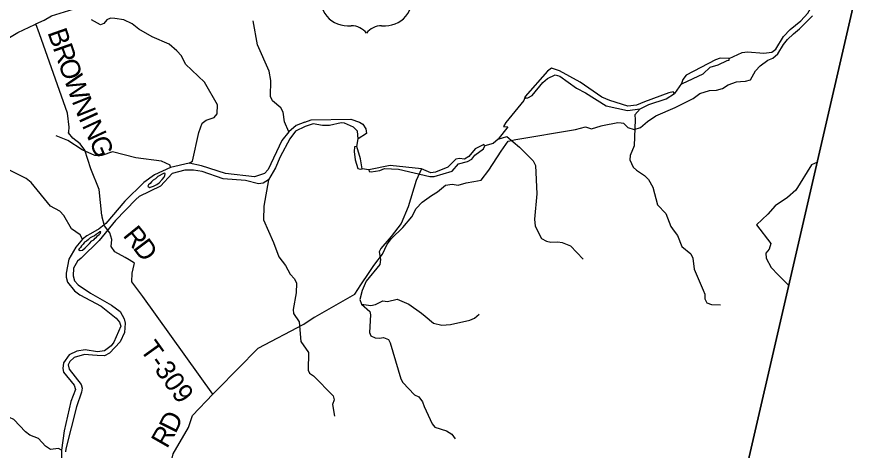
# Model space of a CAD drawing. Extents: x 1525783 to 1900577, y 218250 to 627376.
# Drawn here: x 1716205 to 1729274, y 441556 to 448212 of the extents above; entities that cross this region are included whole.
import ezdxf

# ---------------------------------------------------------------- set-up
doc = ezdxf.new("R2010")
doc.units = 0
for name, color, linetype in [('GM_X_Adjacent_County', 7, 'Continuous'), ('GM_X_County', 7, 'Continuous'), ('GM_X_Major_River', 7, 'Continuous'), ('GM_X_Minor_River', 7, 'Continuous'), ('GM_X_Township', 7, 'Continuous'), ('GM_X_Township_Road', 7, 'Continuous'), ('GM_X_Township_Road_Text', 7, 'Continuous'), ('GM_X_US_Route', 7, 'Continuous'), ('GM_X_US_Shield', 7, 'Continuous')]:
    doc.layers.add(name, color=color, linetype=linetype)

msp = doc.modelspace()

# ---------------------------------------------------------------- linework, layer by layer
at = {"layer": 'GM_X_Adjacent_County'}
msp.add_lwpolyline([(1727145, 440204), (1729274, 449424)], dxfattribs=at)
at = {"layer": 'GM_X_County'}
msp.add_lwpolyline([(1729274, 449424), (1727145, 440204)], dxfattribs=at)
at = {"layer": 'GM_X_Major_River'}
for points in [[(1727131, 447578), (1727328, 447668), (1727409, 447677), (1727661, 447657), (1727783, 447676), (1727846, 447719), (1727963, 447914), (1728063, 448021), (1728231, 448156), (1728337, 448271), (1728405, 448390), (1728503, 448708)], [(1727131, 447578), (1726992, 447580), (1726922, 447558), (1726472, 447321), (1726421, 447254), (1726400, 447192)], [(1726416, 447192), (1726731, 447342), (1726840, 447443), (1726961, 447478), (1727098, 447544)], [(1727098, 447544), (1727127, 447552), (1727131, 447578)], [(1726203, 447048), (1725829, 446914), (1725710, 446860), (1725577, 446845), (1725300, 446931), (1725177, 446985), (1724845, 447212), (1724527, 447388), (1724405, 447428), (1724343, 447380), (1724002, 446992)], [(1724042, 446971), (1724105, 447008), (1724270, 447207), (1724343, 447270), (1724462, 447327), (1724532, 447308), (1724790, 447122), (1724925, 447048), (1725243, 446850), (1725572, 446777), (1725763, 446803), (1725898, 446873), (1726164, 446958), (1726290, 447041)], [(1726400, 447192), (1726290, 447041)], [(1726400, 447192), (1726416, 447192)], [(1724002, 446992), (1723978, 446932), (1723704, 446596), (1723669, 446534), (1723735, 446528), (1723584, 446341), (1723511, 446274), (1723380, 446236)], [(1724002, 446992), (1724011, 446968), (1724042, 446971)], [(1726290, 447041), (1726271, 447063), (1726203, 447048)], [(1720621, 446599), (1720486, 446550), (1720374, 446449), (1720269, 446321), (1720058, 445873), (1719999, 445814), (1719850, 445759), (1719402, 445811), (1719035, 445932), (1718847, 445971), (1718557, 445902), (1718315, 445794), (1718152, 445673), (1717860, 445389), (1717565, 445047), (1717463, 444963), (1717333, 444887), (1717278, 444856), (1717209, 444807), (1717107, 444684), (1717001, 444500), (1716961, 444286), (1716957, 444224), (1716980, 444145), (1717086, 444013), (1717167, 443953), (1717494, 443777), (1717725, 443594), (1717778, 443533), (1717795, 443468), (1717692, 443227), (1717651, 443168), (1717545, 443091), (1717441, 443075), (1717251, 443105), (1717122, 443087), (1717003, 443031), (1716916, 442906), (1716907, 442822), (1716918, 442766), (1717082, 442566), (1717101, 442497), (1717031, 442316), (1716926, 441864), (1716885, 441566), (1716894, 441305)], [(1720621, 446599), (1720719, 446638), (1721326, 446648), (1721458, 446602), (1721510, 446568), (1721555, 446495), (1721566, 446425), (1721438, 446346)], [(1720748, 446575), (1720626, 446531)], [(1721438, 446346), (1721430, 446460), (1721369, 446521), (1721231, 446585), (1721177, 446588), (1720996, 446548), (1720892, 446549), (1720748, 446575)], [(1720626, 446531), (1720478, 446461), (1720390, 446345), (1720240, 446067), (1720171, 445897), (1720061, 445715), (1719982, 445662), (1719910, 445655), (1719708, 445705), (1719368, 445729), (1719045, 445845), (1718913, 445866), (1718777, 445866), (1718586, 445811), (1718407, 445620), (1718080, 445457), (1718027, 445412), (1717718, 445093), (1717465, 444784), (1717188, 444514), (1717133, 444465), (1717072, 444358), (1717064, 444242), (1717087, 444167), (1717144, 444106), (1717332, 443976), (1717655, 443792), (1717786, 443697), (1717848, 443584), (1717864, 443515), (1717852, 443375), (1717785, 443228), (1717625, 443056), (1717546, 443017), (1717436, 443019), (1717364, 443026), (1717242, 443037), (1717080, 442989), (1717017, 442930), (1716992, 442879), (1717007, 442812), (1717187, 442576), (1717206, 442520), (1717196, 442458), (1717116, 442232), (1716955, 441591), (1716948, 441541)], [(1721416, 446224), (1721438, 446346)], [(1721384, 446220), (1721375, 446148), (1721394, 446020), (1721434, 445891)], [(1721416, 446224), (1721384, 446220)], [(1721498, 445884), (1721476, 446037), (1721416, 446224)], [(1723365, 446259), (1723234, 446191), (1723138, 446072), (1723069, 446031), (1722995, 446043), (1722935, 446032), (1722815, 445909), (1722623, 445834), (1722551, 445824), (1722479, 445851), (1722410, 445886), (1721931, 445933), (1721602, 445868)], [(1721639, 445840), (1721772, 445856), (1721841, 445888), (1722055, 445877), (1722538, 445768), (1722606, 445766), (1722882, 445846), (1722976, 445963), (1723115, 445998), (1723183, 446033), (1723226, 446093), (1723362, 446191)], [(1723362, 446191), (1723380, 446236)], [(1723380, 446236), (1723365, 446259)], [(1718367, 445765), (1718329, 445733), (1718295, 445710), (1718268, 445684), (1718246, 445658), (1718223, 445637), (1718213, 445619), (1718237, 445600), (1718301, 445617), (1718352, 445645), (1718388, 445668), (1718433, 445720), (1718461, 445755), (1718472, 445781), (1718478, 445805), (1718474, 445819), (1718452, 445812)], [(1718452, 445812), (1718367, 445765)], [(1721434, 445891), (1721471, 445878), (1721498, 445884)], [(1721602, 445868), (1721498, 445884)], [(1721602, 445868), (1721608, 445841), (1721639, 445840)], [(1717351, 444777), (1717383, 444796), (1717403, 444818), (1717424, 444838), (1717442, 444858), (1717464, 444877), (1717487, 444895), (1717491, 444917), (1717475, 444917), (1717449, 444896), (1717418, 444876), (1717394, 444858)], [(1717394, 444858), (1717358, 444839), (1717329, 444823), (1717299, 444802), (1717269, 444774), (1717242, 444758), (1717218, 444727), (1717195, 444703), (1717177, 444677), (1717150, 444645), (1717172, 444633), (1717208, 444638), (1717249, 444672), (1717292, 444714), (1717316, 444741), (1717351, 444777)]]:
    msp.add_lwpolyline(points, dxfattribs=at)
at = {"layer": 'GM_X_Minor_River'}
for points in [[(1718847, 445971), (1718898, 446002), (1718992, 446442), (1719043, 446584), (1719104, 446631), (1719229, 446669), (1719274, 446726), (1719279, 446868), (1719081, 447213), (1718792, 447491), (1718728, 447616), (1718659, 447692), (1718539, 447798), (1718276, 447909), (1718072, 448025), (1717969, 448110), (1717846, 448170), (1717706, 448192), (1717640, 448196), (1717582, 448171), (1717538, 448111), (1717488, 448094), (1717347, 448171)], [(1720374, 446449), (1720309, 446607), (1720289, 446754), (1720251, 446821), (1720126, 446929), (1720095, 446994), (1720100, 447237), (1720071, 447382), (1719892, 447786), (1719825, 448154)], [(1725763, 446803), (1725680, 446714), (1725689, 446641), (1725673, 446236), (1725611, 446089), (1725608, 446020), (1725656, 445908), (1725708, 445865), (1725833, 445783), (1725892, 445720), (1725961, 445601), (1726031, 445331), (1726157, 445201), (1726235, 445000), (1726284, 444929), (1726335, 444860), (1726401, 444694), (1726539, 444582), (1726572, 444514), (1726592, 444343), (1726732, 444024), (1726755, 443962), (1726758, 443889), (1726787, 443829), (1726859, 443802), (1726997, 443796)], [(1718557, 445902), (1718554, 445940), (1718419, 446001), (1718025, 446054), (1717670, 446143), (1717506, 446090), (1717400, 446088), (1717205, 446177), (1716985, 446318), (1716806, 446391)], [(1723584, 446341), (1723717, 446381), (1723913, 446214), (1724123, 446005), (1724158, 445933), (1724180, 445501), (1724142, 445112), (1724151, 445002), (1724252, 444816), (1724326, 444775), (1724396, 444760), (1724502, 444763), (1724566, 444756), (1724697, 444704), (1724889, 444497)], [(1728484, 445987), (1728392, 445945), (1728150, 445555), (1728026, 445446), (1727834, 445318), (1727724, 445191), (1727549, 445023), (1727770, 444741), (1727742, 444651), (1727691, 444588), (1727698, 444513), (1727774, 444372), (1727879, 444258), (1728047, 444094)], [(1717209, 444807), (1717174, 444874), (1717040, 444964), (1716921, 445167), (1716860, 445235), (1716719, 445309), (1716424, 445674), (1716347, 445737), (1716081, 445870)], [(1722410, 445886), (1722327, 445703), (1722207, 445299), (1722097, 445046), (1721944, 444847), (1721787, 444661), (1721762, 444609), (1721781, 444494), (1721770, 444414), (1721562, 444162), (1721501, 444018), (1721465, 443880), (1721490, 443810), (1721634, 443790), (1721705, 443803), (1721816, 443858), (1721886, 443851), (1722037, 443883), (1722216, 443809), (1722412, 443668), (1722464, 443623), (1722592, 443517), (1722724, 443485), (1722855, 443494), (1723150, 443562), (1723223, 443595), (1723294, 443655)], [(1720061, 445715), (1719990, 445313), (1719988, 445102), (1720139, 444752), (1720221, 444534), (1720325, 444400), (1720397, 444266), (1720462, 444199), (1720490, 444132), (1720485, 443980), (1720443, 443724), (1720445, 443665), (1720533, 443537), (1720560, 443234)], [(1721490, 443810), (1721617, 443694), (1721628, 443644), (1721614, 443373), (1721632, 443322), (1721699, 443292), (1721763, 443285), (1721826, 443298), (1721902, 443267), (1721927, 443216), (1722093, 442665), (1722123, 442608), (1722304, 442417), (1722368, 442384), (1722423, 442311), (1722450, 442239), (1722574, 441972), (1722614, 441920), (1722793, 441865), (1722873, 441812), (1722928, 441743)], [(1720560, 443234), (1720678, 443066), (1720672, 442797), (1720690, 442747), (1720753, 442708), (1721057, 442403), (1721071, 442338), (1721042, 442269), (1721073, 442092)], [(1716885, 441566), (1716843, 441593), (1716716, 441581), (1716643, 441629), (1716535, 441747), (1716404, 441798), (1716335, 441847), (1716156, 442041), (1716021, 442101), (1715896, 442200), (1715840, 442279), (1715762, 442333), (1715651, 442373), (1715582, 442416), (1715438, 442443), (1715230, 442368), (1715033, 442368), (1714967, 442363), (1714842, 442349)]]:
    msp.add_lwpolyline(points, dxfattribs=at)
at = {"layer": 'GM_X_Township'}
msp.add_lwpolyline([(1729274, 449424), (1727145, 440204)], dxfattribs=at)
at = {"layer": 'GM_X_Township_Road'}
for points in [[(1725165, 446543), (1725167, 446544), (1725187, 446550), (1725420, 446596), (1725473, 446588), (1725510, 446582), (1725575, 446519), (1725671, 446489), (1725768, 446519), (1725878, 446609), (1726004, 446695), (1726299, 446824), (1726579, 446962), (1726681, 447042), (1726830, 447085), (1726936, 447091), (1727027, 447114), (1727116, 447170), (1727242, 447220), (1727304, 447223), (1727378, 447228), (1727459, 447250), (1727534, 447389), (1727603, 447465), (1727723, 447549), (1727798, 447583), (1727876, 447650), (1727961, 447789), (1728022, 447866), (1728118, 447953), (1728206, 448034), (1728275, 448099), (1728302, 448124), (1728408, 448233)], [(1716548, 447956), (1716495, 448106)], [(1716998, 446449), (1716999, 446451), (1717004, 446522), (1716979, 446737), (1716548, 447956), (1716548, 447956)], [(1717509, 445165), (1717508, 445167), (1717463, 445565), (1717335, 445883), (1717243, 446169), (1717172, 446269), (1717060, 446354), (1716997, 446435), (1716998, 446449)], [(1721605, 444292), (1721605, 444292), (1721679, 444400), (1721811, 444577), (1721884, 444728), (1721948, 444817), (1722122, 444983), (1722264, 445149), (1722326, 445276), (1722421, 445375), (1722565, 445474), (1722654, 445531), (1722779, 445631), (1722881, 445649), (1722971, 445633), (1723096, 445671), (1723215, 445689), (1723324, 445709), (1723443, 445864), (1723633, 446153), (1723738, 446308), (1723859, 446334), (1724773, 446489), (1724924, 446529), (1725018, 446497), (1725165, 446543)], [(1717862, 444523), (1717703, 444610), (1717647, 444690), (1717657, 444798), (1717628, 444901), (1717546, 445008), (1717511, 445141), (1717509, 445165)], [(1719209, 442425), (1718135, 443926), (1717968, 444151), (1717971, 444281), (1718001, 444415), (1718009, 444435), (1717924, 444489), (1717863, 444522), (1717862, 444523)], [(1720777, 443613), (1720779, 443614), (1721386, 443960), (1721477, 444105), (1721605, 444292)], [(1719282, 442500), (1719906, 443132), (1720607, 443503), (1720765, 443606), (1720777, 443613)], [(1717461, 440011), (1717461, 440012), (1717641, 440335), (1717817, 440411), (1718166, 440465), (1718318, 440691), (1718502, 440845), (1718518, 441164), (1718601, 441512), (1718833, 441917), (1718898, 442098), (1719209, 442425), (1719282, 442500), (1719282, 442500)]]:
    msp.add_lwpolyline(points, dxfattribs=at)
at = {"layer": 'GM_X_US_Route'}
msp.add_lwpolyline([(1712725, 446220), (1712746, 446224), (1713010, 446279), (1713151, 446332), (1714174, 446865), (1715098, 447364), (1715818, 447742), (1716218, 447975), (1716480, 448098), (1716495, 448106), (1716619, 448165), (1716735, 448229), (1717268, 448397), (1720312, 448498), (1722678, 448841)], dxfattribs=at)
at = {"layer": 'GM_X_US_Shield'}
for p, q in [((1721275, 448080), (1721333, 448080)), ((1721797, 448080), (1721855, 448080))]:
    msp.add_line(p, q, dxfattribs=at)
for centre, radius, start, end in [((1721270, 448486), 406, 154.8319, 270.6383), ((1721859, 448486), 406, 269.3617, 25.1681), ((1721333, 447790), 290, 36.8699, 90), ((1721797, 447790), 290, 90, 143.1301)]:
    msp.add_arc(centre, radius, start, end, dxfattribs=at)

# ---------------------------------------------------------------- texts
at = {"layer": 'GM_X_Township_Road_Text'}
for s, rotation, p in [('B', 289.3742, (1716669, 447977)), ('R', 289.3744, (1716751, 447745)), ('O', 289.375, (1716832, 447513)), ('W', 289.5051, (1716920, 447263)), ('N', 291.8272, (1717041, 446923)), ('I', 294.5942, (1717145, 446663)), ('N', 294.8551, (1717197, 446550)), ('G', 293.0015, (1717307, 446313)), ('R', 309.0085, (1717819, 444858)), ('D', 306.765, (1717973, 444669)), ('T-309', 305.6353, (1718083, 443112)), ('D', 63.4757, (1718636, 441812)), ('R', 60.2914, (1718506, 441582))]:
    msp.add_text(s, height=300, rotation=rotation, dxfattribs=at).set_placement(p)

doc.saveas('drawing.dxf')
